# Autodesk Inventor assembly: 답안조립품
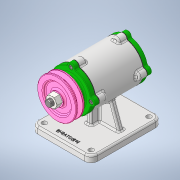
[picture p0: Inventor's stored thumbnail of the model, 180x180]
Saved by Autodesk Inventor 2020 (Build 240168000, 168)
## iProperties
Created: 2022-11
Part Number: 답안조립품
Document SubType Name: Assembly
Designer: owner
Author: owner
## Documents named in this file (12)
- C:\Users\owner\Desktop\721108V1020\답안조립품.iam
- C:\Users\owner\Desktop\721108V1020\본체.ipt
- C:\Users\owner\Desktop\721108V1020\V-벨트풀리.ipt
- C:\Users\owner\Desktop\721108V1020\개스킷.ipt
- C:\Users\owner\Desktop\721108V1020\너트 M12 x 1.25.ipt
- C:\Users\owner\Desktop\721108V1020\뒤커버.ipt
- C:\Users\owner\Desktop\721108V1020\베어링 6204.ipt
- C:\Users\owner\Desktop\721108V1020\볼트 M4 x 12.ipt
- C:\Users\owner\Desktop\721108V1020\앞커버.ipt
- C:\Users\owner\Desktop\721108V1020\오일 실.ipt
- C:\Users\owner\Desktop\721108V1020\축.ipt
- C:\Users\owner\Desktop\721108V1020\키 4 x 4.ipt
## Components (8 placed, 6 different names)
1. V-벨트풀리:1
2. 개스킷:1
3. KS B 1012 클래스 1 일반 - 미터 M12x1.25:1
4. KS B 2023 6204 - 20 x 47 x 14:1
5. KS B 2804 D D - 20 32 8:1
6. KS B 1311 (I) 4 x 4 x 12:1
7. KS B 2023 6204 - 20 x 47 x 14:2
8. 개스킷:2
